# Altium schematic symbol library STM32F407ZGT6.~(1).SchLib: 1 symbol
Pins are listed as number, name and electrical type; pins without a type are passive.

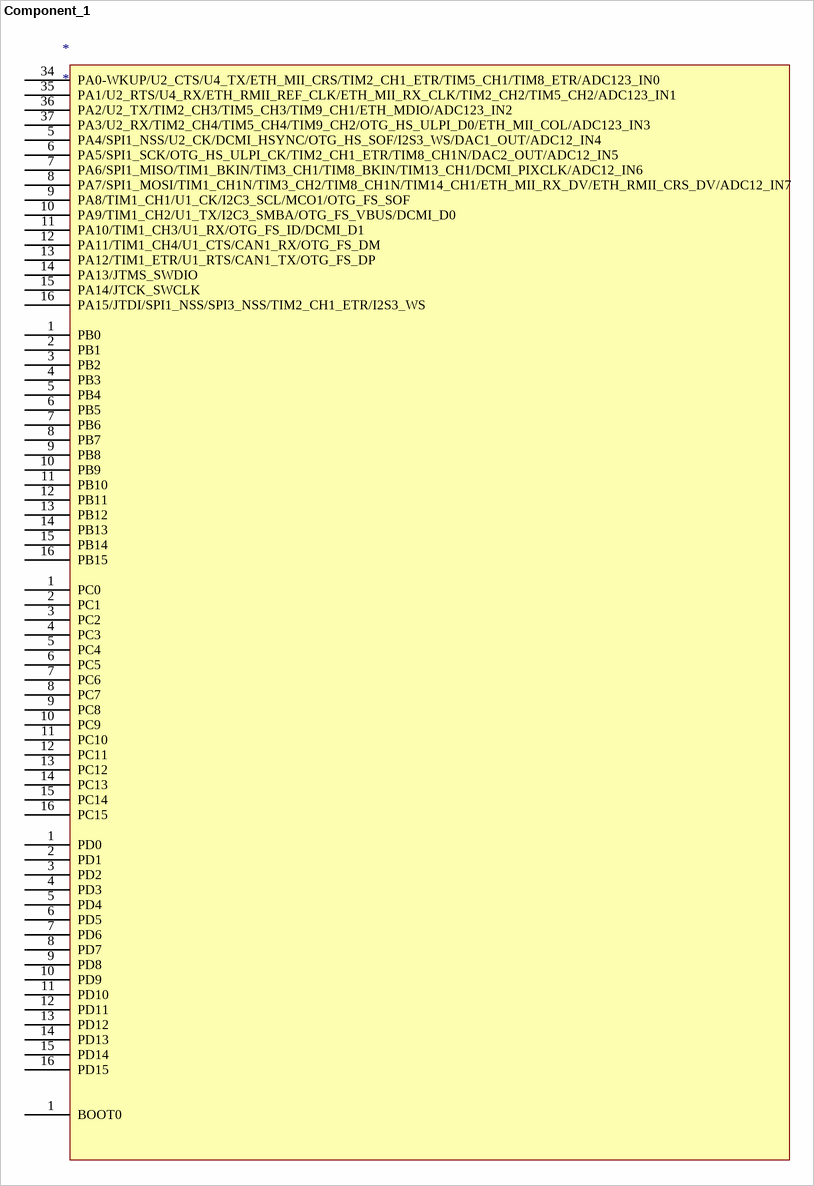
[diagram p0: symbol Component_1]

## Component_1
designator *
pins: 1 PB0, 1 PC0, 1 PD0, 1 BOOT0, 2 PB1, 2 PC1, 2 PD1, 3 PB2, 3 PC2, 3 PD2, 4 PB3, 4 PC3, 4 PD3, 5 PA4/SPI1_NSS/U2_CK/DCMI_HSYNC/OTG_HS_SOF/I2S3_WS/DAC1_OUT/ADC12_IN4, 5 PB4, 5 PC4, 5 PD4, 6 PA5/SPI1_SCK/OTG_HS_ULPI_CK/TIM2_CH1_ETR/TIM8_CH1N/DAC2_OUT/ADC12_IN5, 6 PB5, 6 PC5, 6 PD5, 7 PA6/SPI1_MISO/TIM1_BKIN/TIM3_CH1/TIM8_BKIN/TIM13_CH1/DCMI_PIXCLK/ADC12_IN6, 7 PB6, 7 PC6, 7 PD6, 8 PA7/SPI1_MOSI/TIM1_CH1N/TIM3_CH2/TIM8_CH1N/TIM14_CH1/ETH_MII_RX_DV/ETH_RMII_CRS_DV/ADC12_IN7, 8 PB7, 8 PC7, 8 PD7, 9 PA8/TIM1_CH1/U1_CK/I2C3_SCL/MCO1/OTG_FS_SOF, 9 PB8, 9 PC8, 9 PD8, 10 PA9/TIM1_CH2/U1_TX/I2C3_SMBA/OTG_FS_VBUS/DCMI_D0, 10 PB9, 10 PC9, 10 PD9, 11 PA10/TIM1_CH3/U1_RX/OTG_FS_ID/DCMI_D1, 11 PB10, 11 PC10, 11 PD10, 12 PA11/TIM1_CH4/U1_CTS/CAN1_RX/OTG_FS_DM, 12 PB11, 12 PC11, 12 PD11, 13 PA12/TIM1_ETR/U1_RTS/CAN1_TX/OTG_FS_DP, 13 PB12, 13 PC12, 13 PD12, 14 PA13/JTMS_SWDIO, 14 PB13, 14 PC13, 14 PD13, 15 PA14/JTCK_SWCLK, 15 PB14, 15 PC14, 15 PD14, 16 PA15/JTDI/SPI1_NSS/SPI3_NSS/TIM2_CH1_ETR/I2S3_WS, 16 PB15, 16 PC15, 16 PD15, 34 PA0-WKUP/U2_CTS/U4_TX/ETH_MII_CRS/TIM2_CH1_ETR/TIM5_CH1/TIM8_ETR/ADC123_IN0, 35 PA1/U2_RTS/U4_RX/ETH_RMII_REF_CLK/ETH_MII_RX_CLK/TIM2_CH2/TIM5_CH2/ADC123_IN1, 36 PA2/U2_TX/TIM2_CH3/TIM5_CH3/TIM9_CH1/ETH_MDIO/ADC123_IN2, 37 PA3/U2_RX/TIM2_CH4/TIM5_CH4/TIM9_CH2/OTG_HS_ULPI_D0/ETH_MII_COL/ADC123_IN3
